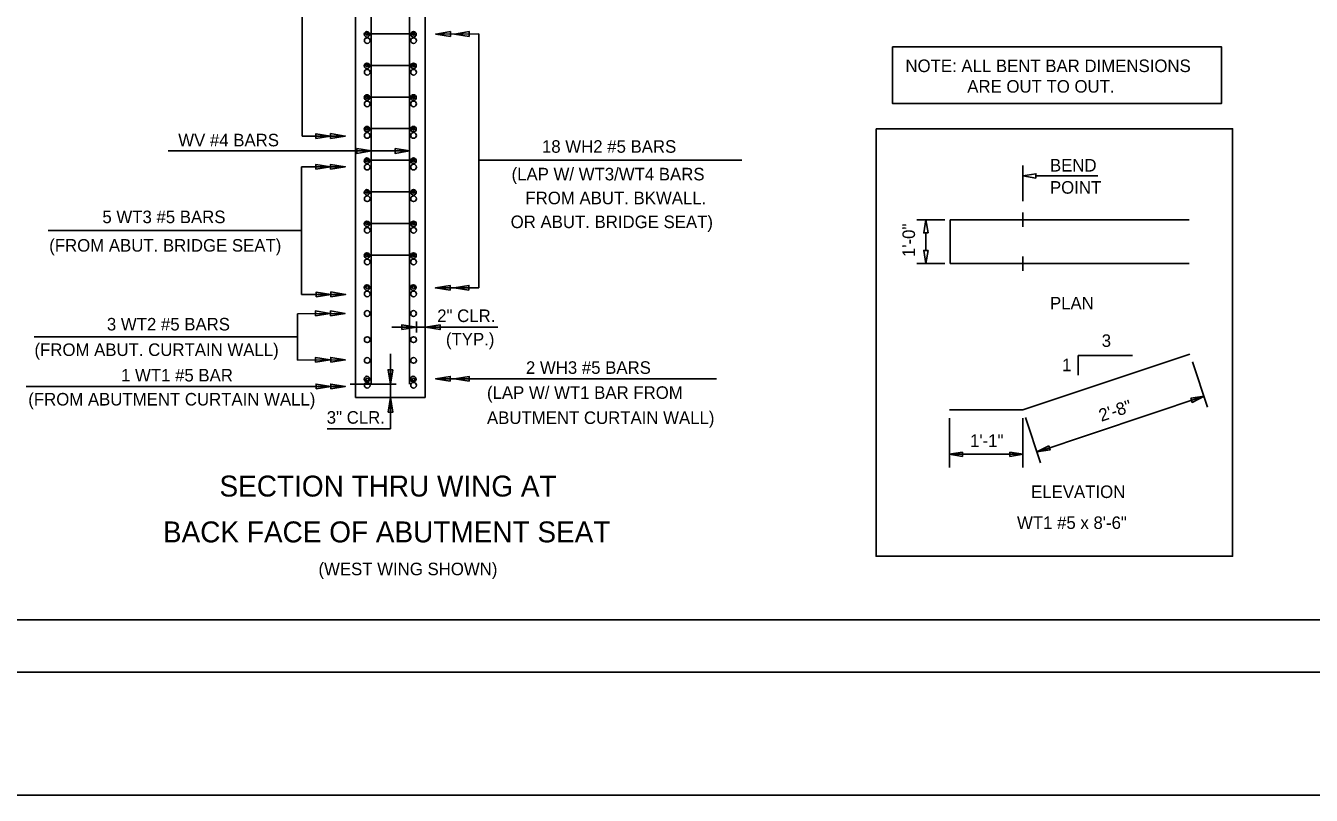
# Model space of a CAD drawing. Extents: x 2146724 to 2153191, y 139029 to 143935.
# Drawn here: x 2147174.72 to 2147223.9, y 143589.78 to 143619.2 of the extents above; entities that cross this region are included whole.
import ezdxf

# ---------------------------------------------------------------- set-up
doc = ezdxf.new("R2010")
doc.units = 0
for name, color, linetype in [('4', 7, 'Continuous'), ('Default', 7, 'Continuous'), ('PR_Bridge_Abutment', 7, 'Continuous'), ('PR_Bridge_Rebar', 7, 'Continuous'), ('PR_Bridge_Reinf', 7, 'Continuous'), ('PR_Dimensions', 7, 'Continuous'), ('PTX_36_LEADER', 7, 'Continuous'), ('SHT_Plot_Shape_Full', 7, 'Continuous'), ('SHT_Plot_Shape_Half', 7, 'Continuous'), ('SHT_Sheet_Border', 7, 'Continuous'), ('T', 7, 'Continuous'), ('T-Title', 7, 'Continuous')]:
    doc.layers.add(name, color=color, linetype=linetype)

# ---------------------------------------------------------------- blocks, each defined once
blk = doc.blocks.new('ARROWHD_11')
at = {"layer": 'Default'}
blk.add_lwpolyline([(0.0261, -0.0045), (0.0261, 0.0043), (-0.0004, -0.0001)], close=True, dxfattribs=at)
blk = doc.blocks.new('REINFORCEMENT')
at = {"layer": 'PTX_36_LEADER'}
blk.add_circle((0, 0.106), 0.106, dxfattribs=at)
blk.add_circle((0, 0.106), 0.106, dxfattribs=at)

msp = doc.modelspace()

# ---------------------------------------------------------------- linework, layer by layer
at = {"layer": '4'}
for p, q in [((2147187.341, 143628.482), (2147187.341, 143604.995)), ((2147187.341, 143604.988), (2147190.008, 143604.988))]:
    msp.add_line(p, q, dxfattribs=at)
at = {"layer": 'Defpoints'}
for p, q in [((2147187.789, 143618.887), (2147189.569, 143618.887)), ((2147187.789, 143617.678), (2147189.569, 143617.678)), ((2147187.789, 143616.47), (2147189.569, 143616.47)), ((2147187.789, 143615.262), (2147189.569, 143615.262)), ((2147187.789, 143614.053), (2147189.569, 143614.053)), ((2147187.789, 143612.845), (2147189.569, 143612.845)), ((2147187.789, 143611.637), (2147189.569, 143611.637)), ((2147187.789, 143610.428), (2147189.569, 143610.428)), ((2147187.128, 143605.488), (2147188.45, 143605.488))]:
    msp.add_line(p, q, dxfattribs=at)
at = {"layer": 'PR_Bridge_Abutment'}
for p, q in [((2147187.341, 143629.335), (2147187.341, 143604.988)), ((2147190.008, 143629.082), (2147190.008, 143604.988)), ((2147187.341, 143604.988), (2147190.008, 143604.988))]:
    msp.add_line(p, q, dxfattribs=at)
at = {"layer": 'PR_Bridge_Rebar'}
for p, q in [((2147219.229, 143611.773), (2147210.092, 143611.773)), ((2147210.092, 143611.773), (2147210.092, 143610.107)), ((2147219.229, 143610.107), (2147210.092, 143610.107)), ((2147212.868, 143604.518), (2147219.253, 143606.646)), ((2147210.062, 143604.518), (2147212.868, 143604.518))]:
    msp.add_line(p, q, dxfattribs=at)
at = {"layer": 'PR_Bridge_Reinf'}
for p, q in [((2147187.942, 143628.797), (2147187.942, 143605.488)), ((2147189.407, 143628.797), (2147189.407, 143605.488))]:
    msp.add_line(p, q, dxfattribs=at)
for centre in [(2147187.788, 143618.626), (2147189.56, 143618.626), (2147187.788, 143617.417), (2147189.56, 143617.417), (2147187.788, 143616.209), (2147189.56, 143616.209), (2147187.788, 143615.001), (2147189.56, 143615.001), (2147187.788, 143613.792), (2147189.56, 143613.792), (2147187.788, 143612.584), (2147189.56, 143612.584), (2147187.788, 143611.376), (2147189.56, 143611.376), (2147187.788, 143610.167), (2147189.56, 143610.167), (2147187.788, 143608.943), (2147189.56, 143608.943), (2147187.788, 143608.195), (2147189.56, 143608.195), (2147187.788, 143607.195), (2147189.56, 143607.195), (2147187.788, 143606.404), (2147189.56, 143606.404), (2147187.788, 143605.451), (2147189.56, 143605.451)]:
    msp.add_circle(centre, 0.109, dxfattribs=at)
at = {"layer": 'PR_Dimensions'}
for p, q in [((2147185.291, 143628.49), (2147185.291, 143614.979)), ((2147190.542, 143618.879), (2147192.06, 143618.881)), ((2147192.06, 143618.881), (2147192.06, 143609.176)), ((2147186.948, 143614.978), (2147185.291, 143614.979)), ((2147180.168, 143614.409), (2147189.409, 143614.409)), ((2147202.114, 143614.057), (2147192.06, 143614.057)), ((2147186.809, 143613.804), (2147185.27, 143613.806)), ((2147185.27, 143613.806), (2147185.27, 143608.925)), ((2147212.868, 143612.491), (2147212.868, 143613.856)), ((2147213.368, 143613.455), (2147215.738, 143613.455)), ((2147212.868, 143611.513), (2147212.868, 143612.058)), ((2147208.813, 143611.773), (2147209.886, 143611.773)), ((2147175.576, 143611.365), (2147185.27, 143611.365)), ((2147209.16, 143611.273), (2147209.16, 143610.607)), ((2147208.813, 143610.107), (2147209.886, 143610.107)), ((2147212.868, 143609.831), (2147212.868, 143610.372)), ((2147190.397, 143609.175), (2147192.06, 143609.176)), ((2147186.955, 143608.927), (2147185.27, 143608.928)), ((2147186.948, 143608.198), (2147185.114, 143608.189)), ((2147185.114, 143608.189), (2147185.114, 143606.413)), ((2147188.723, 143607.672), (2147192.788, 143607.674)), ((2147189.671, 143607.885), (2147189.671, 143607.475)), ((2147175.038, 143607.301), (2147185.114, 143607.301)), ((2147188.676, 143606.653), (2147188.675, 143603.786)), ((2147186.948, 143606.422), (2147185.114, 143606.413)), ((2147214.984, 143606.588), (2147214.984, 143605.844)), ((2147217.06, 143606.588), (2147214.984, 143606.588)), ((2147219.928, 143604.621), (2147219.354, 143606.345)), ((2147190.403, 143605.699), (2147201.145, 143605.698)), ((2147186.948, 143605.406), (2147174.736, 143605.405)), ((2147188.895, 143605.489), (2147188.457, 143605.489)), ((2147219.792, 143605.029), (2147213.408, 143602.9)), ((2147210.062, 143602.313), (2147210.062, 143604.2)), ((2147212.868, 143602.313), (2147212.868, 143604.2)), ((2147213.543, 143602.493), (2147212.969, 143604.217)), ((2147188.675, 143603.786), (2147186.257, 143603.787)), ((2147212.868, 143602.813), (2147210.062, 143602.813))]:
    msp.add_line(p, q, dxfattribs=at)
for points in [[(2147190.969, 143618.786), (2147190.409, 143618.879), (2147190.969, 143618.973)], [(2147191.688, 143618.786), (2147191.128, 143618.879), (2147191.688, 143618.973)], [(2147207.886, 143618.39), (2147220.462, 143618.39), (2147220.462, 143616.217), (2147207.886, 143616.217)], [(2147185.823, 143614.881), (2147186.383, 143614.974), (2147185.823, 143615.068)], [(2147186.383, 143614.884), (2147186.943, 143614.978), (2147186.383, 143615.071)], [(2147207.253, 143615.258), (2147220.888, 143615.258), (2147220.888, 143598.916), (2147207.253, 143598.916)], [(2147187.384, 143614.502), (2147187.944, 143614.409), (2147187.384, 143614.315)], [(2147188.849, 143614.502), (2147189.409, 143614.409), (2147188.849, 143614.315)], [(2147185.822, 143613.708), (2147186.382, 143613.801), (2147185.822, 143613.894)], [(2147186.382, 143613.711), (2147186.942, 143613.804), (2147186.382, 143613.897)], [(2147213.368, 143613.372), (2147213.368, 143613.538), (2147212.868, 143613.455)], [(2147209.244, 143611.273), (2147209.077, 143611.273), (2147209.16, 143611.773)], [(2147209.244, 143610.607), (2147209.077, 143610.607), (2147209.16, 143610.107)], [(2147190.957, 143609.082), (2147190.397, 143609.175), (2147190.957, 143609.268)], [(2147191.676, 143609.082), (2147191.116, 143609.175), (2147191.676, 143609.268)], [(2147185.835, 143608.83), (2147186.395, 143608.924), (2147185.835, 143609.017)], [(2147186.395, 143608.833), (2147186.955, 143608.927), (2147186.395, 143609.02)], [(2147185.801, 143608.105), (2147186.361, 143608.198), (2147185.801, 143608.292)], [(2147186.381, 143608.104), (2147186.941, 143608.198), (2147186.381, 143608.291)], [(2147189.111, 143607.579), (2147189.671, 143607.673), (2147189.111, 143607.766)], [(2147190.57, 143607.766), (2147190.01, 143607.673), (2147190.57, 143607.579)], [(2147185.808, 143606.329), (2147186.368, 143606.423), (2147185.808, 143606.516)], [(2147186.388, 143606.329), (2147186.948, 143606.422), (2147186.388, 143606.515)], [(2147188.769, 143606.048), (2147188.676, 143605.488), (2147188.582, 143606.048)], [(2147190.963, 143605.605), (2147190.403, 143605.699), (2147190.963, 143605.792)], [(2147191.682, 143605.605), (2147191.122, 143605.699), (2147191.682, 143605.792)], [(2147185.828, 143605.312), (2147186.388, 143605.406), (2147185.828, 143605.499)], [(2147186.388, 143605.312), (2147186.948, 143605.406), (2147186.388, 143605.499)], [(2147188.582, 143604.428), (2147188.676, 143604.988), (2147188.769, 143604.428)]]:
    msp.add_lwpolyline(points, close=True, dxfattribs=at)
msp.add_lwpolyline([(2147190.57, 143607.673), (2147192.461, 143607.673)], dxfattribs=at)
for centre in [(2147187.789, 143618.887), (2147187.789, 143618.887), (2147189.56, 143618.887), (2147189.56, 143618.887), (2147187.789, 143617.678), (2147187.789, 143617.678), (2147189.56, 143617.678), (2147189.56, 143617.678), (2147187.789, 143616.47), (2147187.789, 143616.47), (2147189.56, 143616.47), (2147189.56, 143616.47), (2147187.789, 143615.262), (2147187.789, 143615.262), (2147189.56, 143615.262), (2147189.56, 143615.262), (2147187.789, 143614.053), (2147187.789, 143614.053), (2147189.56, 143614.053), (2147189.56, 143614.053), (2147187.789, 143612.845), (2147187.789, 143612.845), (2147189.56, 143612.845), (2147189.56, 143612.845), (2147187.789, 143611.637), (2147187.789, 143611.637), (2147189.56, 143611.637), (2147189.56, 143611.637), (2147187.789, 143610.428), (2147187.789, 143610.428), (2147189.56, 143610.428), (2147189.56, 143610.428), (2147187.789, 143609.204), (2147187.789, 143609.204), (2147189.56, 143609.204), (2147189.56, 143609.204), (2147187.789, 143605.671), (2147187.789, 143605.671), (2147187.789, 143605.671), (2147189.56, 143605.671), (2147189.56, 143605.671), (2147189.56, 143605.671)]:
    msp.add_circle(centre, 0.0533, dxfattribs=at)
for centre, start, end in [((2147187.789, 143618.887), 0, 180), ((2147189.56, 143618.887), 0, 180), ((2147187.789, 143618.887), 180, 0), ((2147189.56, 143618.887), 180, 0), ((2147187.789, 143617.678), 0, 180), ((2147187.789, 143617.678), 180, 0), ((2147189.56, 143617.678), 0, 180), ((2147189.56, 143617.678), 180, 0), ((2147187.789, 143616.47), 0, 180), ((2147187.789, 143616.47), 180, 0), ((2147189.56, 143616.47), 0, 180), ((2147189.56, 143616.47), 180, 0), ((2147187.789, 143615.262), 0, 180), ((2147187.789, 143615.262), 180, 0), ((2147189.56, 143615.262), 0, 180), ((2147189.56, 143615.262), 180, 0), ((2147187.789, 143614.053), 0, 180), ((2147187.789, 143614.053), 180, 0), ((2147189.56, 143614.053), 0, 180), ((2147189.56, 143614.053), 180, 0), ((2147187.789, 143612.845), 0, 180), ((2147187.789, 143612.845), 180, 0), ((2147189.56, 143612.845), 0, 180), ((2147189.56, 143612.845), 180, 0), ((2147187.789, 143611.637), 0, 180), ((2147187.789, 143611.637), 180, 0), ((2147189.56, 143611.637), 0, 180), ((2147189.56, 143611.637), 180, 0), ((2147187.789, 143610.428), 0, 180), ((2147187.789, 143610.428), 180, 0), ((2147189.56, 143610.428), 0, 180), ((2147189.56, 143610.428), 180, 0), ((2147187.789, 143609.204), 0, 180), ((2147187.789, 143609.204), 180, 0), ((2147189.56, 143609.204), 0, 180), ((2147189.56, 143609.204), 180, 0), ((2147187.789, 143605.671), 0, 180), ((2147187.789, 143605.671), 180, 0), ((2147189.56, 143605.671), 0, 180), ((2147189.56, 143605.671), 180, 0)]:
    msp.add_arc(centre, 0.0533, start, end, dxfattribs=at)
at = {"layer": 'SHT_Plot_Shape_Full'}
msp.add_lwpolyline([(2147114.94, 143685.779), (2147258.94, 143685.779), (2147258.94, 143589.779), (2147114.94, 143589.779)], close=True, dxfattribs=at)
at = {"layer": 'SHT_Plot_Shape_Half'}
msp.add_lwpolyline([(2147121.49, 143682.479), (2147257.49, 143682.479), (2147257.49, 143594.479), (2147121.49, 143594.479)], close=True, dxfattribs=at)
at = {"layer": 'SHT_Sheet_Border'}
msp.add_lwpolyline([(2147255.29, 143596.479), (2147129.29, 143596.479), (2147129.29, 143680.479), (2147255.29, 143680.479)], close=True, dxfattribs=at)

# ---------------------------------------------------------------- block references
at = {"layer": 'PR_Bridge_Reinf', "rotation": 152.99999999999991}
for p in [(2147187.825, 143618.963), (2147189.605, 143618.963), (2147187.825, 143617.754), (2147189.605, 143617.754), (2147187.825, 143616.546), (2147189.605, 143616.546), (2147187.825, 143615.338), (2147189.605, 143615.338), (2147187.825, 143614.129), (2147189.605, 143614.129), (2147187.825, 143612.921), (2147189.605, 143612.921), (2147187.825, 143611.713), (2147189.605, 143611.713), (2147187.825, 143610.504), (2147189.605, 143610.504), (2147187.825, 143609.28), (2147189.596, 143609.28)]:
    msp.add_blockref('REINFORCEMENT', p, dxfattribs=at)
at = {"layer": 'PR_Bridge_Reinf', "yscale": -1, "rotation": -152.99999999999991}
for p in [(2147187.825, 143605.595), (2147189.596, 143605.595)]:
    msp.add_blockref('REINFORCEMENT', p, dxfattribs=at)
at = {"layer": 'PR_Dimensions'}
for p, xscale, yscale, rotation in [((2147219.792, 143605.029), 18.89760000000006, 18.89760000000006, -161.5650515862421), ((2147212.868, 143602.813), 18.897599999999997, 18.897599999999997, 180), ((2147213.415, 143602.902), 18.89760000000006, -18.897599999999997, 18.434948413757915)]:
    msp.add_blockref('ARROWHD_11', p, dxfattribs=dict(at, xscale=xscale, yscale=yscale, rotation=rotation))
at = {"layer": 'PR_Dimensions', "xscale": 18.897599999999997, "yscale": -18.897599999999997}
msp.add_blockref('ARROWHD_11', (2147210.062, 143602.813), dxfattribs=at)

# ---------------------------------------------------------------- texts
at = {"layer": 'T'}
for s, p in [('NOTE: ALL BENT BAR DIMENSIONS', (2147208.376, 143617.424)), ('ARE OUT TO OUT.', (2147210.741, 143616.638)), ('WV #4 BARS', (2147180.557, 143614.585)), ('18 WH2 #5 BARS', (2147194.471, 143614.34)), ('BEND', (2147213.904, 143613.622)), ('(LAP W/ WT3/WT4 BARS', (2147193.308, 143613.284)), ('POINT', (2147213.904, 143612.775)), ('FROM ABUT. BKWALL.', (2147193.838, 143612.372)), ('5 WT3 #5 BARS', (2147177.655, 143611.649)), ('OR ABUT. BRIDGE SEAT)', (2147193.273, 143611.46)), ('(FROM ABUT. BRIDGE SEAT)', (2147175.62, 143610.56)), ('PLAN', (2147213.904, 143608.352)), ('2" CLR.', (2147190.463, 143607.869)), ('3 WT2 #5 BARS', (2147177.826, 143607.547)), ('(TYP.)', (2147190.797, 143606.974)), ('3', (2147215.884, 143606.918)), ('(FROM ABUT. CURTAIN WALL)', (2147175.056, 143606.571)), ('2 WH3 #5 BARS', (2147193.857, 143605.889)), ('1', (2147214.365, 143605.99)), ('1 WT1 #5 BAR', (2147178.367, 143605.596)), ('(FROM ABUTMENT CURTAIN WALL)', (2147174.819, 143604.678)), ('(LAP W/ WT1 BAR FROM', (2147192.367, 143604.932)), ('3" CLR.', (2147186.237, 143603.983)), ('ABUTMENT CURTAIN WALL)', (2147192.367, 143603.972)), ('1\'-1"', (2147210.847, 143603.096)), ('ELEVATION', (2147213.183, 143601.142)), ('WT1 #5 x 8\'-6"', (2147212.644, 143599.958)), ('(WEST WING SHOWN)', (2147185.921, 143598.19))]:
    msp.add_text(s, height=0.48, dxfattribs=at).set_placement(p)
for s, rotation, p in [('1\'-0"', 90, (2147208.742, 143610.353)), ('2\'-8"', 18.4349, (2147215.868, 143604.054))]:
    msp.add_text(s, height=0.48, rotation=rotation, dxfattribs=at).set_placement(p)
at = {"layer": 'T-Title'}
for s, p in [('SECTION THRU WING AT', (2147182.134, 143601.198)), ('BACK FACE OF ABUTMENT SEAT', (2147179.971, 143599.446))]:
    msp.add_text(s, height=0.8, dxfattribs=at).set_placement(p)

doc.saveas('drawing.dxf')
